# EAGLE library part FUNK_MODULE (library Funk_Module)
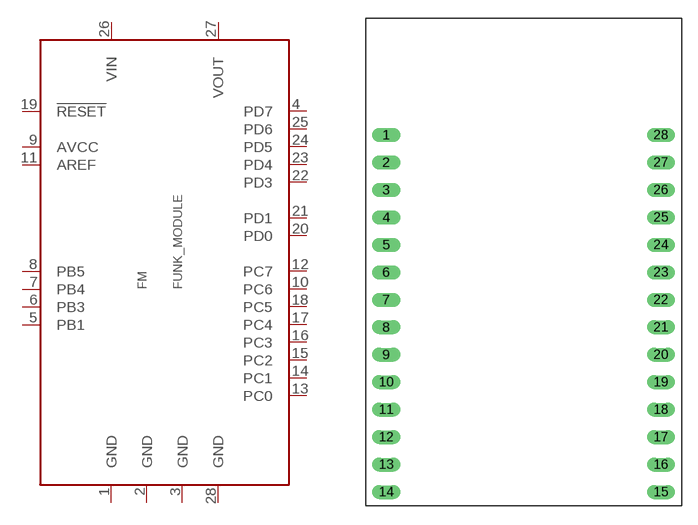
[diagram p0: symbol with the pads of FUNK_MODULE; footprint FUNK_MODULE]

Designator prefix FM

## FUNK_MODULE  [FUNK_MODULE]
1  GND  pwr
2  GND  pwr
3  GND  pwr
4  PD7
5  PB1
6  PB3
7  PB4
8  PB5
9  AVCC
10  PC6
11  AREF
12  PC7
13  PC0
14  PC1
15  PC2
16  PC3
17  PC4
18  PC5
19  !RESET
20  PD0
21  PD1
22  PD3
23  PD4
24  PD5
25  PD6
26  VIN  pwr
27  VOUT  pwr
28  GND  pwr

## Footprint FUNK_MODULE (pad centres in mm)
drill 0.8 long: 1 -13.335,10.16; 2 -13.335,7.62; 3 -13.335,5.08; 4 -13.335,2.54; 5 -13.335,0; 6 -13.335,-2.54; 7 -13.335,-5.08; 8 -13.335,-7.62; 9 -13.335,-10.16; 10 -13.335,-12.7; 11 -13.335,-15.24; 12 -13.335,-17.78; 13 -13.335,-20.32; 14 -13.335,-22.86; 15 12.065,-22.86; 16 12.065,-20.32; 17 12.065,-17.78; 18 12.065,-15.24; 19 12.065,-12.7; 20 12.065,-10.16; 21 12.065,-7.62; 22 12.065,-5.08; 23 12.065,-2.54; 24 12.065,0; 25 12.065,2.54; 26 12.065,5.08; 27 12.065,7.62; 28 12.065,10.16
